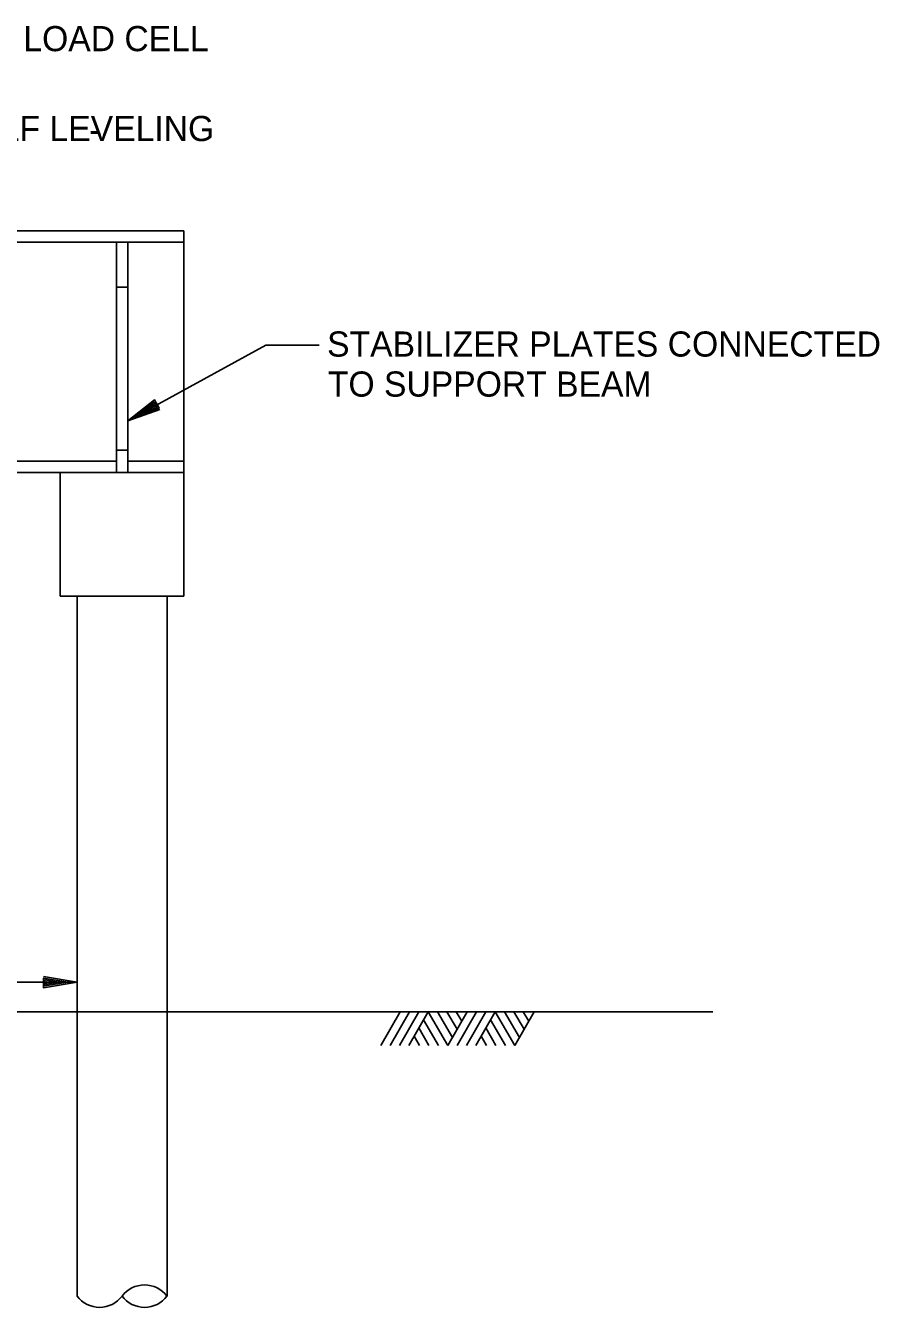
# Model space of a CAD drawing. Extents: x 22369.6 to 22413.6, y 22369.6 to 22403.6.
# Drawn here: x 22383.87 to 22388.62, y 22376.79 to 22383.92 of the extents above; entities that cross this region are included whole.
import ezdxf

# ---------------------------------------------------------------- set-up
doc = ezdxf.new("R2010")
doc.units = 0
for name, color, linetype in [('Level 1', 7, 'Continuous'), ('Level 2', 7, 'Continuous'), ('Level 4', 7, 'Continuous'), ('Level 7', 7, 'Continuous')]:
    doc.layers.add(name, color=color, linetype=linetype)

msp = doc.modelspace()

# ---------------------------------------------------------------- linework, layer by layer
at = {"layer": 'Level 1'}
for p, q in [((22384.4832, 22381.7459), (22384.4832, 22381.7459)), ((22384.4376, 22381.7208), (22384.4376, 22381.7208)), ((22384.1563, 22378.5989), (22382.3282, 22378.5989)), ((22384.1043, 22378.5989), (22384.1043, 22378.5989)), ((22384.1563, 22378.5989), (22384.1563, 22378.5989)), ((22385.8442, 22378.2471), (22385.9525, 22378.4346)), ((22385.8962, 22378.2471), (22386.0045, 22378.4346)), ((22385.9482, 22378.2471), (22386.0565, 22378.4346)), ((22386.0001, 22378.2471), (22386.1084, 22378.4346)), ((22386.1646, 22378.2471), (22386.0824, 22378.3896)), ((22386.2166, 22378.2471), (22386.1084, 22378.4346)), ((22386.2426, 22378.2921), (22386.1604, 22378.4346)), ((22386.2686, 22378.3371), (22386.2124, 22378.4346)), ((22386.2166, 22378.2471), (22386.3249, 22378.4344)), ((22386.2946, 22378.3821), (22386.2644, 22378.4346)), ((22386.2686, 22378.2471), (22386.377, 22378.4346)), ((22386.3205, 22378.2471), (22386.4289, 22378.4346)), ((22386.3725, 22378.2471), (22386.4809, 22378.4346)), ((22386.5371, 22378.2471), (22386.4549, 22378.3896)), ((22386.5891, 22378.2471), (22386.4809, 22378.4346)), ((22386.6151, 22378.2921), (22386.5329, 22378.4346)), ((22386.6411, 22378.3371), (22386.5849, 22378.4346)), ((22386.5891, 22378.2471), (22386.6975, 22378.4346)), ((22386.6671, 22378.3821), (22386.6369, 22378.4346)), ((22386.1126, 22378.2471), (22386.0564, 22378.3446)), ((22386.4851, 22378.2471), (22386.4289, 22378.3446)), ((22386.0607, 22378.2471), (22386.0305, 22378.2996)), ((22386.4332, 22378.2471), (22386.403, 22378.2996))]:
    msp.add_line(p, q, dxfattribs=at)
for points in [[(22384.4376, 22381.7208), (22385.2061, 22382.1429), (22385.5024, 22382.1429)], [(22384.6164, 22381.7837), (22384.4376, 22381.7208), (22384.5866, 22381.838), (22384.6121, 22381.7916), (22384.4832, 22381.7459), (22384.5844, 22381.8254), (22384.6008, 22381.7956), (22384.527, 22381.7699), (22384.5822, 22381.8128), (22384.5889, 22381.8005), (22384.5726, 22381.795)], [(22383.9693, 22378.6299), (22384.1563, 22378.5989), (22383.9693, 22378.5679), (22383.9693, 22378.6209), (22384.1043, 22378.5989), (22383.9773, 22378.5779), (22383.9773, 22378.6119), (22384.0543, 22378.5989), (22383.9853, 22378.5879), (22383.9853, 22378.6019), (22384.0023, 22378.5989)]]:
    msp.add_lwpolyline(points, dxfattribs=at)
at = {"layer": 'Level 2'}
for p, q in [((22384.3751, 22382.715), (22384.3751, 22381.4337)), ((22384.4376, 22382.715), (22384.4376, 22381.4337)), ((22384.3751, 22382.465), (22384.4376, 22382.465)), ((22384.3751, 22381.5587), (22384.4376, 22381.5587)), ((22380.1251, 22378.4337), (22387.6902, 22378.4337)), ((22384.1563, 22378.4337), (22384.1563, 22376.8528)), ((22384.6563, 22378.4337), (22384.6563, 22376.8528))]:
    msp.add_line(p, q, dxfattribs=at)
for centre, radius, start, end in [((22384.531, 22376.7592), 0.156, 36.84504, 143.15496), ((22384.2812, 22376.9465), 0.1561, 216.87181, 323.12819), ((22384.531, 22376.9466), 0.1561, 216.90623, 323.09376)]:
    msp.add_arc(centre, radius, start, end, dxfattribs=at)
at = {"layer": 'Level 7'}
for p, q in [((22380.6407, 22382.7775), (22384.7501, 22382.7775)), ((22384.7501, 22381.4337), (22384.7501, 22382.7775)), ((22380.6407, 22382.715), (22384.7501, 22382.715)), ((22380.6407, 22381.4962), (22384.3751, 22381.4962)), ((22384.4376, 22381.4962), (22384.7501, 22381.4962)), ((22380.6407, 22381.4337), (22384.0626, 22381.4337)), ((22384.0626, 22381.4337), (22384.0626, 22380.7462)), ((22384.0626, 22381.4337), (22384.7501, 22381.4337)), ((22384.7501, 22381.4337), (22384.7501, 22380.7462)), ((22384.7501, 22380.7462), (22384.0626, 22380.7462)), ((22384.1563, 22380.7462), (22384.1563, 22378.4337)), ((22384.6563, 22380.7462), (22384.6563, 22378.4337))]:
    msp.add_line(p, q, dxfattribs=at)

# ---------------------------------------------------------------- texts
at = {"layer": 'Level 2'}
msp.add_text('-', height=0.14, dxfattribs=at).set_placement((22384.2237, 22383.2712))
at = {"layer": 'Level 4'}
for s, p in [('ELECTRICAL STRAIN GAGE LOAD CELL', (22381.3191, 22383.7774)), ('HYDRAULIC JACK WITH SELF LEVELING', (22381.2879, 22383.2775)), ('STABILIZER PLATES CONNECTED', (22385.5462, 22382.0786)), ('TO SUPPORT BEAM', (22385.5504, 22381.856))]:
    msp.add_text(s, height=0.14, dxfattribs=at).set_placement(p)

doc.saveas('drawing.dxf')
